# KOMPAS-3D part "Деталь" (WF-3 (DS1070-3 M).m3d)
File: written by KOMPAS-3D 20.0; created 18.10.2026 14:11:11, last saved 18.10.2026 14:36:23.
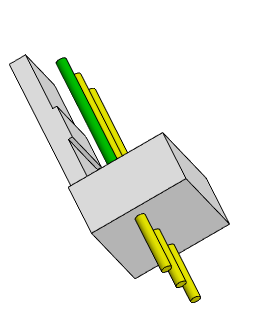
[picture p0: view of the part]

Document properties: Полное имя файла: D:\myProjects\Progect_esp32\box_compas\разъемы\WF-3 (DS1070-3 M).m3d

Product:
- Part/product: Деталь
    Масса: 0.00147109

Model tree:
1. Эскиз:1
2. Элемент выдавливания:1
     Расстояние 1 = 7.62
3. Эскиз:2  (with: Элемент выдавливания:1)
4. Элемент выдавливания:2
     Расстояние 2 = 1.27
5. Эскиз:3  (with: Элемент выдавливания:1)
6. Элемент выдавливания:3
     Расстояние 2 = 1.27
7. Эскиз:4  (with: Элемент выдавливания:1)
8. Элемент выдавливания:4
     Расстояние 1 = 3.4
9. Массив по сетке:1  (with: Элемент выдавливания:4, Эскиз:4)  (3 pattern instances)
     Шаг 1 = 2.54; Угол раствора = 90
10. Эскиз:5  (with: Элемент выдавливания:1, Элемент выдавливания:4, Элемент выдавливания:2, Элемент выдавливания:3)
11. Элемент выдавливания:5
     Расстояние 1 = 7.15
12. Массив по сетке:3  (with: Элемент выдавливания:5, Эскиз:5, Элемент выдавливания:1)  (3 pattern instances)
     Шаг 1 = 2.54; Угол раствора = 90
